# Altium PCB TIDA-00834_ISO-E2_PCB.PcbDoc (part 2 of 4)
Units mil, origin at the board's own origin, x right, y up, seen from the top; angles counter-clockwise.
Board outline 9055.12 x 4133.86 mil, 4 copper layers (Top Layer, GND, PWR, Bottom Layer), stack 61.92 mil thick; 647 components, 282 nets, 1430 pads, 409 vias.
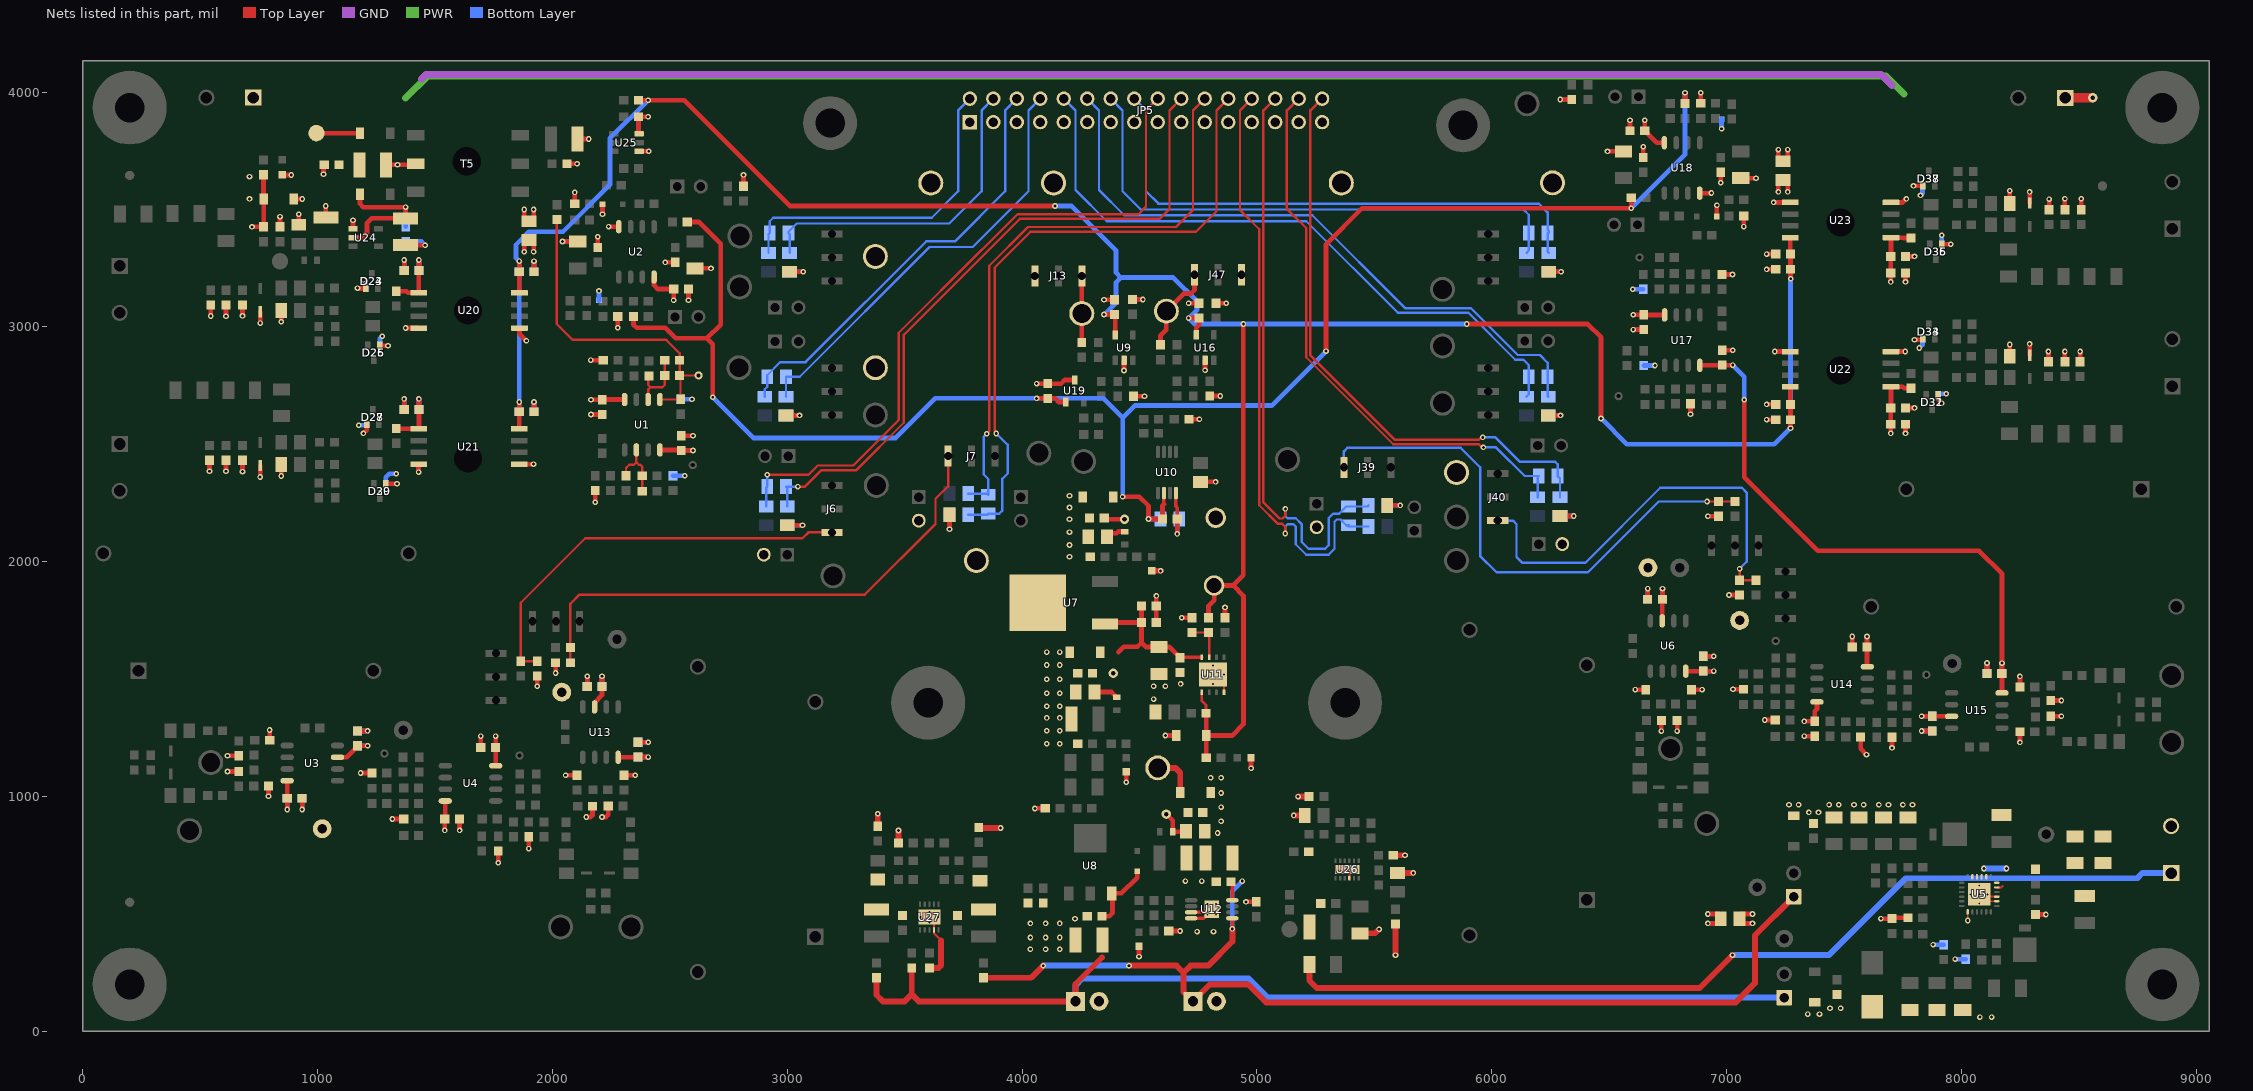
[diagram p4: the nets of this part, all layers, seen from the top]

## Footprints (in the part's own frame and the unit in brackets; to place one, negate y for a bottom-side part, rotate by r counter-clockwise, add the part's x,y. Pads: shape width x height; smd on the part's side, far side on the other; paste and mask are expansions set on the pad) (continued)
DIO_SOD323 [mm] "TVS DIODE, SOD323, SMT"
  rect 1.2x0.35 smd: 1(-1.25,0) 2(1.25,0)
  Top Layer region: -0.356,0.25 -0.357,-0.227 0.417,-0.227 0.415,0.25
  silkscreen extent -5.03,-0.65 1.25,0.65, body extent -1.25,-0.63 1.25,0.63, height 1.1
DSC0010J [mm] "SON, 10-Leads, Body 3x3mm, Pitch 0.5mm, Thermal Pad 2.4x1.65mm, TI Recommended"
  rrect100% 0.6x0.24 smd: 1(-1.4,1) 2(-1.4,0.5) 3(-1.4,0) 4(-1.4,-0.5) 5(-1.4,-1) 6(1.4,-1) 7(1.4,-0.5) 8(1.4,0) 9(1.4,0.5) 10(1.4,1)
  rrect6% 1.65x2.4 smd paste-0.825: 11(0,0)
  silkscreen extent -1.7,-1.7 1.7,1.7, body extent -1.57,-1.57 1.57,1.57, height 0.81
DSS0012B [mm] "SON, 12-Leads, Body 2x3mm, Pitch 0.5mm, Thermal Pad 2.65x1.0mm, TI Recommended"
  rrect40% 0.5x0.25 smd: 1(-0.95,1.25) 2(-0.95,0.75) 3(-0.95,0.25) 4(-0.95,-0.25) 5(-0.95,-0.75) 6(-0.95,-1.25) 7(0.95,-1.25) 8(0.95,-0.75) 9(0.95,-0.25) 10(0.95,0.25) 11(0.95,0.75) 12(0.95,1.25)
  rrect11% 0.949x1.168 on Top Paste: 13(0,0.684) 13(0,-0.684)
  rrect11% 1x2.65 smd paste-0.5: 13(0,0)
  silkscreen extent -1.05,-1.7 1.05,1.7, body extent -1,-1.5 1,1.5, height 0.81
DWV0008A [mm] "SOIC, 8-Leads, Body 5.95x7.6mm (max), Pitch 1.27mm"
  rrect17% 1.8x0.6 smd: 1(-5.45,1.905) 2(-5.45,0.635) 3(-5.45,-0.635) 4(-5.45,-1.905) 5(5.45,-1.905) 6(5.45,-0.635) 7(5.45,0.635) 8(5.45,1.905)
  silkscreen extent -6.25,-2.95 2.98,2.95, body extent -5.77,-2.92 5.77,2.93, height 2.67
FCC_disclaimer [mil]
Fiducial10-20 [mm]
  round 1 smd mask+0.5: 1(0,0)
  Top Layer keep-out circle w1.178: c0,0 r0.5
HDR100_1X2 [mil]
  rect 60x60 hole 38: 1(0,0)
  round 60 hole 38: 2(100,0)
  silkscreen extent -50,-50 150,50
IEC_HighVoltage_Large [mil]
  silkscreen extent -365,-159 323,250
IND_VLF504012 [mm] "TDK"
  rect 1.3x2.2 smd: 1(-1.45,0) 2(1.45,0)
  silkscreen extent -2.2,-2.7 2.2,2.7, body extent -2.15,-2.65 2.15,2.65, height 1.2
Keystone1573-2#1 [mm] "Double Turret"
  round 2.7 hole 2.05: 1(0,0)
  silkscreen extent -1.73,-1.73 1.73,1.73, body extent -1.18,-1.18 1.17,1.18, height 4.72
Keystone1573-2#2 [mm] "Double Turret"
  round 2.7 hole 2.05: 1(4.318,13.335)
  silkscreen extent 2.59,11.61 6.05,15.06, body extent 3.14,12.16 5.49,14.51, height 4.72
Keystone5001 [mil] "For Keystone 500x miniature loop terminals"
  round 80 hole 40: 1(0,0)
  silkscreen extent -58,-58 58,58, body extent -49,-49 49,49, height 182
Keystone5002 [mil] "For Keystone 500x miniature loop terminals"
  round 80 hole 40: 1(0,0)
  silkscreen extent -58,-58 58,58, body extent -49,-49 49,49, height 182
Keystone5010 [mil] "Keystone Multipurpose loops"
  round 87 hole 63: 1(0,0)
  silkscreen extent -70,-70 70,70, body extent -63,-63 63,62, height 319
Keystone5126 [mil] "Keystone Multipurpose loops"
  round 87 hole 63: 1(0,0)
  silkscreen extent -70,-70 70,70, body extent -63,-63 63,62, height 319
Keystone_1891 [mil] "3/16 Hex Female Standoff"
  body extent -108,-93 108,94, height 245
Keystone_1902C#1 [mil] "Hex Standoff, 4-40 threaded, nylon"
  body extent -145,-126 146,126, height 501
Keystone_1902C#2 [mil] "Hex Standoff, 4-40 threaded, nylon"
  round 1 on Mech4: 0(0,0)
  body extent -145,-126 146,126, height 501
KVU_1 [mm]
  rect 1.2x2.8 smd: 1(-2.29,-3.635) 3(2.29,-3.635)
  rect 6.096x6.096 smd: 2(0,3.635)
  silkscreen extent -4.62,-6.78 3.43,7.22
Label_650x200 [mil] "Thermal Transfer Label"
  silkscreen extent -325,-100 325,100, body extent -325,-100 325,100, height 1
LED0603AA [mil]
  rect 32x32 smd: 1(-32.48,0) 2(32.48,0)
  silkscreen extent -16,-74 58,16
"LG L29K_GREEN" [mm] "OSRAM"
  rect 0.8x0.8 smd: 1(-0.75,0) 2(0.75,0)
  silkscreen extent -0.1,-0.5 1.45,0.5, body extent -0.9,-0.45 0.9,0.45, height 0.67
MMZ1608_095 [mm] "TDK"
  rect 0.6x0.8 smd: 1(-0.7,0) 2(0.7,0)
  silkscreen extent -0.15,-0.58 0.15,0.58, body extent -0.87,-0.47 0.87,0.47, height 0.95
"NY PMS 440 0025 PH" [mm] "4-40 nylon screw and mounting hole"
  round 8 hole 3.2: 1(0,0)
  body extent -3.3,-3.3 3.3,3.3, height 2.69
Pb-Free_Overlay_Small [mil]
  silkscreen extent -46,-46 46,46
PogoPad [mil] "No Solder Paste"
  round 70 smd paste-35: 1(0,0)
POWERMITE [mil] "On Semi recommended land pattern, 457-04.pdf Rev 04E dated 2008-11-26"
  rect 105x100 smd: 1(-46,0)
  rect 30x50 smd: 2(46,0)
  silkscreen extent -124,-63 61,63, body extent -94,-40 59,40, height 45
RGE0024B [mm] "QFN, 24-Leads, Body 4x4mm, Pitch 0.5mm, Thermal Pad 2.45x2.45mm, TI Recommended"
  oval 0.6x0.24 smd: 1(-1.9,1.25) 2(-1.9,0.75) 3(-1.9,0.25) 4(-1.9,-0.25) 5(-1.9,-0.75) 6(-1.9,-1.25) 13(1.9,-1.25) 14(1.9,-0.75) 15(1.9,-0.25) 16(1.9,0.25) 17(1.9,0.75) 18(1.9,1.25)
  oval 0.24x0.6 smd: 7(-1.25,-1.9) 8(-0.75,-1.9) 9(-0.25,-1.9) 10(0.25,-1.9) 11(0.75,-1.9) 12(1.25,-1.9) 19(1.25,1.9) 20(0.75,1.9) 21(0.25,1.9) 22(-0.25,1.9) 23(-0.75,1.9) 24(-1.25,1.9)
  rect 2.45x2.45 smd paste-1.225: 25(0,0)
  silkscreen extent -2.22,-2.22 2.22,2.22, body extent -2.07,-2.07 2.07,2.07, height 1.01
Samtec_SSW-116-01-x-D [mm] "Receptacle, 2.54mm, 16x2, TH"
  rect 1.55x1.55 hole 1.04: 1(-19.05,1.27)
  round 1.55 hole 1.04: 2(-19.05,-1.27) 3(-16.51,1.27) 4(-16.51,-1.27) 5(-13.97,1.27) 6(-13.97,-1.27) 7(-11.43,1.27) 8(-11.43,-1.27) 9(-8.89,1.27) 10(-8.89,-1.27) 11(-6.35,1.27) 12(-6.35,-1.27) 13(-3.81,1.27) 14(-3.81,-1.27) 15(-1.27,1.27) 16(-1.27,-1.27) 17(1.27,1.27) 18(1.27,-1.27) 19(3.81,1.27) 20(3.81,-1.27) 21(6.35,1.27) 22(6.35,-1.27) 23(8.89,1.27) 24(8.89,-1.27) 25(11.43,1.27) 26(11.43,-1.27) 27(13.97,1.27) 28(13.97,-1.27) 29(16.51,1.27) 30(16.51,-1.27) 31(19.05,1.27) 32(19.05,-1.27)
  silkscreen extent -20.57,-2.48 20.57,2.8, body extent -20.57,-2.48 20.57,2.48, height 8.51
SDC08A [mm] "SON, 8-Leads, Body 4x4mm, Pitch 0.8mm, NSC Recommended"
  rect 0.6x0.3 smd paste-0.15 mask+0.051: 1(-1.9,1.2) 2(-1.9,0.4) 3(-1.9,-0.4) 4(-1.9,-1.2) 5(1.9,-1.2) 6(1.9,-0.4) 7(1.9,0.4) 8(1.9,1.2)
  rect 2.6x3 smd paste-1.5 mask+0.051: 9(0,0)
  silkscreen extent -3.02,-2.2 2.35,2.2, body extent -2.05,-2.05 2.05,2.05, height 0.8
SOD-123 [mm] "On Semi recommended land pattern"
  rect 0.915x1.22 smd: 1(-1.637,0) 2(1.637,0)
  silkscreen extent -2.74,-1.17 2.03,1.17, body extent -1.93,-0.9 1.93,0.9, height 1.35
SOD-323 [mm] "NXP recommended land pattern"
  rect 0.6x0.6 smd: 1(-1.1,0) 2(1.1,0)
  silkscreen extent -2.06,-0.86 1.53,0.86, body extent -1.3,-0.67 1.3,0.68, height 1.1
sod-323 [mm] "NXP recommended land pattern"
  rect 0.6x0.6 smd: 1(-1.1,0) 2(1.1,0)
  silkscreen extent -2.06,-0.86 1.53,0.86, body extent -1.3,-0.67 1.3,0.68, height 1.1
SOT-323 [mm] "Zetex recommended land pattern.  March 2007"
  rect 0.8x0.6 smd: 1(-0.8,0.65) 2(-0.8,-0.65) 3(0.8,0)
  silkscreen extent -1.14,-1.22 0.77,1.22, body extent -1.13,-1.13 1.12,1.12, height 1.13
TE_5-146280-3 [mm] "Header, 2.54mm, 3x1, TH"
  rect 0.76x2.29 hole 0.89: 1(-2.54,0) 2(0,0) 3(2.54,0)
  silkscreen extent -3.9,-1.17 3.61,1.17, body extent -3.61,-1.17 3.61,1.17, height 8.13
TH-40 [mil]
  round 75 hole 40: 1(0,0)
TI_Stacked_Overlay_Small [mil]
  silkscreen extent -418,-98 418,98
TP1_PD40_D0.5_S50 [mil]
  round 40 hole 20: 1(0,0)
  silkscreen extent -25,-25 25,25
TP-040_RND [mil]
  round 70 / inner round 62 / far side round 62 hole 40: 1(0,0)
TP_H045P075 [mil] "TP_H0.45P0.75"
  round 35 hole 17.72: 1(0,0)
TSW-102-07-G-S [mm] "Samtec 100mil, 1x2, 230 mil above insulator"
  rrect6% 1.65x1.65 hole 1.016: 1(-1.27,0)
  round 1.65 hole 1.016: 2(1.27,0)
  silkscreen extent -2.54,-1.27 2.54,1.65, body extent -2.54,-1.27 2.54,1.27, height 8.38
Wurth_750313638 [mm] "SMD, 6-Leads, Body 8x9.14mm, Pitch 3.05mm"
  rect 1.9x1.14 smd: 1(-5.655,3.05) 2(-5.655,0) 3(-5.655,-3.05) 4(5.655,-3.05) 5(5.655,0) 6(5.655,3.05)
  silkscreen extent -4,-4.57 4,4.87, body extent -6.35,-4.57 6.35,4.57, height 7.62
XFMR_CR8350-2500-N [mil] "CURRENT TRANSFORMERS, VERTICAL, 4 PIN, THRU"
  rect 69.06x69.06 / inner round 69.06 / far side rect 69.06x69.06 hole 49.37: 1(-250,500)
  round 69.06 hole 49.37: 2(-250,-500) 3(250,650) 4(250,-650)
  silkscreen extent -317,-738 276,738, body extent -276,-738 276,738, height 1535

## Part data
C1 C2 C4 C5 C19 C20 C82 C84 C88 C90 C99 C100 C101 C102 C104 C105: "CAP, CERM, 100pF, 25V, +/-10%, X7R, 0603"
C3 C6 C9 C66 C103 C106 C110: "CAP, CERM, 0.1uF, 25V, +/-5%, X7R, 0603"
C7 C8 C107 C108: "CAP, CERM, 1000pF, 50V, +/-5%, C0G/NP0, 0603"
C10 C11 C109 C111 C120 C121: "CAP, CERM, 0.01uF, 25V, +/-5%, C0G/NP0, 0603"
C12 C18 C43 C75 C81 C85 C92 C98: library part C1608X5R1C105K, "CAP, CERM, 1 µF, 16 V, +/- 10%, X5R, 0603"
C13 C17 C44 C76 C80 C83 C86 C87 C89 C91 C93 C97: "CAP, CERM, 0.1 µF, 25 V, +/- 10%, X8R, AEC-Q200 Grade 0, 0603"
C14 C16 C47 C52 C77 C79 C94 C96: "CAP, CERM, 1000 pF, 50 V, +/- 10%, X7R, 0603"
C15 C48 C54 C70 C74 C78 C95: library part 06031C103JAT2A, "10000pF 100V Ceramic Capacitor X7R 0603"
C21 C22 C23 C24 C112 C113 C114 C115: "CAP, CERM, 0.01 µF, 50 V, +/- 10%, X7R, 0805"
C25: "CAP, TA, 4.7 µF, 25 V, +/- 10%, 2 ohm, SMD"
C26 C27 C28 C29 C36 C38 C39 C40 C41 C156: "CAP, CERM, 4.7 µF, 25 V, +/- 20%, X7R, 1206"
C30 C33 C35 C42 C159 C161 C163: "CAP, CERM, 0.01 µF, 6.3 V, +/- 10%, X7R, 0603"
C31: library part C0603C224K4RACTU, "CAP, CERM, 0.22 µF, 6.3 V, +/- 10%, X7R, 0603"
C32 C34: "CAP, CERM, 10 pF, 50 V, +/- 5%, C0G/NP0, 0603"
C37 C152 C154 C158 C165: "CAP, CERM, 1 µF, 25 V, +/- 10%, X5R, 0603"
C45 C55 C68: library part C2012X5R1H475K125AB, "CAP, CERM, 4.7uF, 50V, +/-10%, X5R, 0805"
C46 C51 C56 C58 C69 C71 C118 C119: "CAP, CERM, 0.1uF, 50V, +/-10%, X7R, 0603"
C49 C50: library part GRM188R61H105KAALD, "CAP, CERM, 1uF, 50V, +/-10%, X5R, 0603"
C53 C116: "CAP, CERM, 0.1uF, 16V, +/-5%, X7R, 0603"
C57 C60 C67 C72: "CAP, CERM, 10uF, 35V, +/-20%, X7R, 1210"
C59: "CAP, CERM, 0.47uF, 50V, 10%, X5R, 0603"
C61 C62: "CAP, CERM, 1uF, 10V, +/-10%, X7R, 0805"
C63 C117: "CAP, CERM, 0.1uF, 10V, +/-10%, X7R, 0603"
C64: "CAP, CERM, 10uF, 16V, +/-20%, X5R, 0603"
C65: library part GRM31CR71E106KA12L, "CAP, CERM, 10uF, 25V, +/-10%, X7R, 1206"
C73 C153 C155 C160 C162: "CAP, CERM, 2.2uF, 10V, +/-10%, X7R, 0805"
C122 C123 C127 C128 C132 C133 C137 C138: library part 06033C104JAT2A, "CAP, CERM, 0.1uF, 25V, +/-5%, X7R, 0603"
C124 C125 C129 C130 C134 C135 C139 C140: "CAP, CERM, 1 µF, 16 V, +/- 10%, X7R, 0603"
C126 C131 C136 C141: "CAP, CERM, 330 pF, 50 V, +/- 10%, C0G/NP0, 0805"
C142 C146 C147 C149 C151 C157 C164: library part GMK325AB7106MM-T, "CAP, CERM, 10uF, 35V, +/-20%, X7R, 1210"
C143 C145 C148 C150 C167: library part C0603C104K5RACTU, "CAP, CERM, 0.1uF, 50V, +/-10%, X7R, 0603"
C144: library part C2012X5R1H475K125AB, "4.7µF ±10% 50V X5R Ceramic Capacitor -55°C ~ 85°C"
C166: "CAP, CERM, 3.3 µF, 35 V, +/- 10%, X5R, 0603"
D1 D2 D3 D9 D15 D16 D17 D18: "DIODE, TVS, BIDIRECTIONAL, 3.3VWM, 26VC, SOD323"
D4 D7: "Diode, Schottky, 20 V, 1 A, POWERMITE"
D5 D6 D11 D13: "Diode, Zener, 15V, 1W, SOD-123"
D8: library part MMSZ4685-V, "Diode, Zener, 3.6V, 500mW, SOD-123"
D10 D12 D14 D44: "LED, Green, SMD"
D19 D20 D21 D22: "Diode, Switching, 100 V, 0.2 A, SOD-323"
D23 D24 D25 D26 D27 D28 D29 D30 D31 D32 D33 D34 D35 D36 D37 D38: library part BAV99WT1G, "Diode, P-N, 70V, 0.2A, SOT-323"
D39 D43: "Diode, Zener, 5.6 V, 500 mW, SOD-123"
D40: library part "LED_LG L29K-G2J1-24-Z", "LED SmartLED Green 570NM"
D41 D42: library part MBR0520LT1G, "Diode, Schottky, 20V, 0.5A, SOD-123"
D45: "Diode, Ultrafast, 100 V, 0.25 A, SOD-323"
FB1 FB2 FB3 L19: "Ferrite Bead, 1000 ohm @ 100 MHz, 0.3 A, 0603"
FID1 FID2 FID3 FID4 FID5 FID6: "Fiducial mark.  There is nothing to buy or mount."
H1 H2 H3 H4 H13 H15: "Machine Screw, Round, #4-40 x 1/4, Nylon, Philips panhead"
H5 H6 H7 H8 H14 H16: "Standoff, Hex, 0.5\"L #4-40 Nylon"
H9 H11: "MACHINE SCREW PAN PHILLIPS 4-40"
H10 H12: "Hex Standoff, #4-40, Aluminum, 1/4\""
J1 J2 J10 J31 J34 J48 J49: "TERMINAL BLOCK 5.08MM VERT 2POS, TH"
J3 J4 J17 J18 J24 J25 J35 J36: "Header, Male 2-pin, 100mil spacing,"
J5 J6 J7 J8 J9 J13 J14 J28 J30 J39 J40 J45 J46 J47: "Header, 2.54mm, 3x1, Gold, TH"
J11 J12: "Terminal Block, 4x1, 2.54mm, TH"
J15 J16: library part TSW-102-07-G-S, "Header, 100mil, 2x1, Gold, TH"
J20 J21 J22 J23 J37 J38 J41 J42: "Header, 100mil, 2x1, Gold, TH"
JP5: library part SSW-116-01-G-D, "Receptacle, 2.54mm, 16x2, Gold, TH"
L1 L2 L5 L6 L7 L8 L9 L10 L11 L12 L13 L14 L15 L16 L17 L18: "Ferrite Bead, 21 ohm @ 100 MHz, 6 A, 0805"
L3 L4: "Inductor, Shielded, Ferrite, 4.7uH, 1.83A, 0.1 ohm, SMD"
LBL1: library part THT-14-423-10, "Thermal Transfer Printable Labels, 0.650\" W x 0.200\" H - 10,000 per roll"
LOGO: library part IEC_HighVoltage, "IEC 61010-1 High Voltage Warning"
Logo1: library part TI_Logo, "Texas Instrument Corporate Signature"
Logo2: library part Pb-Free
Logo3: library part FCC_disclaimer, "FCC_disclaimer"
R1 R3 R14 R17 R138 R140 R151 R154: "RES, 68.0 k, 1%, 0.1 W, 0603"
R2 R4 R5 R7 R11 R16 R139 R141 R142 R144 R148 R153: "RES, 330 k, 1%, 0.25 W, 1206"
R6 R9 R12 R13 R143 R146 R149 R150: "RES, 16.0 k, 1%, 0.1 W, 0603"
R8 R10 R26 R32 R45 R99 R118 R134 R145 R147 R163 R169 R196 R197: "RES, 100 ohm, 1%, 0.1W, 0603"
R15 R18 R152 R155: "RES, 130 k, 1%, 0.1 W, 0603"
R19 R20 R21 R22 R156 R157 R158 R159 R208 R209 R212 R213 R218 R219 R224 R225: "RES, 649, 1%, 0.1 W, 0603"
R23 R29 R160 R166: "RES, 1.00Meg ohm, 1%, 0.1W, 0603"
R24 R30 R36 R40 R47 R48 R80 R86 R90 R94 R101 R102 R107 R111 R120 R121 R123 R127 R136 R137 R161 R167: "RES, 100 k, 1%, 0.1 W, 0603"
R25 R31 R88 R162 R168: "RES, 10.0k ohm, 1%, 0.1W, 0603"
R27 R33 R82 R164 R170 R203: library part RNCF0603TKY10K0, "RES, 10.0k ohm, 1%, 0.1W, 0603"
R28 R34 R165 R171: "RES, 1.00k ohm, 1%, 0.25W, 1206"
R35 R41 R89 R95 R106 R112 R122 R128: "RES, 249, 0.1%, 0.1 W, 0603"
R37 R91 R108 R124: "RES, 169, 1%, 0.1 W, 0603"
R38 R92 R109 R125: "RES, 5.60 k, 0.1%, 0.1 W, 0603"
R39 R93 R110 R126: "RES, 15.0, 1%, 0.1 W, 0603"
R42 R57 R59 R62 R63 R65 R96 R104 R105 R113 R114 R116 R129 R130 R132 R198 R200 R201 R214 R229 R230 R231 R233 R234 R238 R240 R246 R247: "RES, 0, 5%, 0.1 W, 0603"
R43 R97 R115 R131: "RES, 82.0 k, 0.1%, 0.1 W, 0603"
R44 R46 R98 R100 R117 R119 R133 R135: "RES, 8.20 k, 1%, 0.1 W, 0603"
R49 R50 R51 R52 R53 R54 R55 R56 R173 R174 R175 R176 R177 R178 R179 R180: "RES, 1.00 k, 1%, 0.125 W, 0805"
R58: "RES, 0 ohm, 5%, 0.25W, 1206"
R60: "RES, 576 k, 1%, 0.1 W, 0603"
R61 R66 R67: "RES, 49.9 k, 0.1%, 0.1 W, 0603"
R64: library part RC0603FR-07620KL, "RES SMD 620K OHM 1% 1/10W 0603"
R68: library part RT0603DRE071RL, "RES SMD 1 OHM 5% 1/10W 0603"
R69: "RES, 1.0 k, 5%, 0.1 W, 0603"
R70 R103 R172: library part CRCW0805330KJNEA, "RES, 0 ohm, 5%, 0.125W, 0805"
R71: "RES, 300 ohm, 5%, 0.1W, 0603"
R72 R73 R77 R78 R81 R83 R189 R190 R191 R192 R193 R194 R195 R226 R228 R242 R243 R244: "RES, 0 ohm, 5%, 0.1W, 0603"
R74 R84: "RES, 3.9k ohm, 5%, 0.1W, 0603"
R75 R76: "RES, 2.00 k, 1%, 0.25 W, 1206"
R79: "RES, 8.45 k, 1%, 0.1 W, 0603"
R85: "RES, 1.07 M, 1%, 0.1 W, 0603"
R87: "RES, 31.6k ohm, 1%, 0.1W, 0603"
R181 R182 R183 R184 R185 R186 R187 R188: "RES, 100 k, 1%, 0.125 W, 0805"
R199 R205 R215 R221: "RES, 160 k, 1%, 0.1 W, 0603"
R202 R204 R235 R236: "RES, 249 k, 1%, 0.1 W, 0603"
R206 R207 R210 R211 R216 R217 R222 R223: "RES, 12.0, 1%, 0.1 W, 0603"
R220 R232 R237 R239: "RES, 75.0 k, 1%, 0.1 W, 0603"
R227 R241: "RES, 820, 1%, 0.1 W, 0603"
R245: "RES, 0, 5%, 0.25 W, 1206"
T1 T2 T3 T4: "CURRENT TRANSFORMER, 20-1 KHz, 57 OHM, VERTICAL, THRU-4P"
T5: library part 750313734, "Transformer, 340 uH, TH"
TP1 TP57 TP58: library part PogoPad, "Pad for Pogo Pin Connector"
TP2 TP5 TP6 TP11 TP12 TP13 TP14 TP18 TP21 TP25 TP31 TP32 TP33 TP34 TP35 TP36 TP37 TP38 TP42 TP43 TP46 TP47 TP48 TP49 TP50 TP51 TP52 TP53 TP54 TP55 TP56 TP59 TP60 TP61: library part 1573-2, "Terminal, Turret, TH, Double"
TP3 TP4 TP10 TP17 TP28 TP30 TP41 TP44 TP45: "Test Point, O.040 Hole"
TP7 TP8 TP27 TP39: "Test Point, Miniature, White, TH"
TP9 TP26 TP29 TP40: "Test Point, Miniature, Black, TH"
TP15 TP16: "Test Point,  Black, Thru Hole Color Keyed"
TP19 TP20 TP22: library part TP-040_RND, "Test Point 40mil pad 20mil drill"
TP23: library part 5010, "Test Point, Multipurpose, Red, TH"
TP24: library part 5126, "Test Point, Multipurpose, Green, TH"
U1 U4 U14 U17: "0.03 uV/degC, 6 uV Vos, Low Noise, Rail-to-Rail Output, Zero-Drift Operational Amplifier, 4 to 36 V, -40 to 105 degC, 8-pin SOIC (D0008A), Green (RoHS & no Sb/Br)"
U2 U18: library part LM2903D, "Dual Comparator, D0008A"
U3 U6 U13 U15: library part INA188D, "INA188 Precision, Zero-Drift, Rail-to-Rail Out, High Voltage Instrumentation Amplifier, D0008A"
U5: "Postive and Negative Output DC-DC Converter, 2.7 to 5.5 V, -40 to 85 degC, 24-pin QFN (RGE24), Green (RoHS & no Sb/Br)"
U7: "IC, 300-mA 40-V LOW-DROPOUT REGULATOR WITH 25-uA QUIESCENT CURRENT"
U8: "IC,  vvV, 800mA LDO Voltage Regulators"
U9 U16: "20 MHz, Low Noise, RRIO, CMOS Operational Amplifier with Shutdown, 1.8 to 5.5 V, -40 to 125 degC, 5-pin SOT23 (DBV0005A), Green (RoHS & no Sb/Br)"
U10: "Low Noise, Very Low Drift, Precision Voltage Reference, -40 to 125 degC, 8-pin MSOP(DGK), Green (RoHS & no Sb/Br)"
U11: "Series of Adjustable Micropower Voltage Regulators, 8-pin LLP"
U12: "Single Output High PSRR LDO, 200 mA, Adjustable -1.18 to -33 V Output, -3 to -36 V Input, with Ultra-Low Noise, 8-pin MSOP (DGN), -40 to 125 degC, Green (RoHS & no Sb/Br)"
U19: "2.5 V, 50 ppm / degC, 50 uA Series (Bandgap) Voltage Reference, -40 to 125 degC, 3-pin SOT-23 (DBZ), Green (RoHS & no Sb/Br)"
U20 U21 U22 U23: "200 kHz, Fully-Differential Isolation Amplifier, DWV0008A"
U24: "Single Output LDO, 150 mA, Fixed 5 V Output, 2.5 to 24 V Input, with Ultra-Low IQ, 5-pin SOT-23 (DBV), -40 to 125 degC, Green (RoHS & no Sb/Br)"
U25: "LOW-NOISE 1A TRANSFORMER DRIVERS FOR ISOLATED POWER SUPPLIES, DBV0006A"
U26: "Low-Noise Regulated Switched-Capacitor Voltage Inverter and Positive LDO, DSS0012B"
U27: "Wide-VIN (±33 V), 150-mA, Spilt-Rail Output, Positive and Negative LDO Voltage Regulator with Startup Tracking, DSC0010J"
ZZ1: library part AssemblyNoteLabel
ZZ2 ZZ3 ZZ4: library part AssemblyNote

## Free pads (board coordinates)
  round 0 hole 120 slot 550 at 90 deg unplated mask+5: 2(1635,3705) 2(1640,2440) 2(1640,3070) 2(7484,2814) 2(7484,3444)

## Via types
v1: diameter 24, hole 12, Top Layer to Bottom Layer, tented both sides, 388 vias
v2: diameter 19.68, hole 7.87, Top Layer to Bottom Layer, tented top, 15 vias
v3: diameter 19.68, hole 7.87, Top Layer to Bottom Layer, 5 vias
v4: diameter 40, hole 20, Top Layer to Bottom Layer, 1 vias

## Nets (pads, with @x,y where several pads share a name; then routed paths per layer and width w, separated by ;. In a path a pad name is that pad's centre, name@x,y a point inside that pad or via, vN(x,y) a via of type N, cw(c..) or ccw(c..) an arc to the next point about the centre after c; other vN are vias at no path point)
+2.5V: J13.1 R77.1 TP21.1 | length 283.5
  Top Layer w20: R77.1@4254,2933.5 TP21.1@4254,3057 J13.1@4254,3217
+2.5VB: J47.1 R191.1 TP55.1 | length 376.1
  Top Layer w20: R191.1@4589,2923.5 4589,2962 4614,2987 TP55.1@4614,3067 4689,3142 4719,3142 4734,3157 J47.1@4734,3222
+3.3V: C45.1 C46.1 C62.1 C118.1 C119.1 D8.1 FB1.2 R25.2 R31.2 R162.2 R168.2 TP19.1 U10.2 U19.1 | length 7682
  Top Layer w15: 4603.8,2245.2 U10.2@4603.8,2292.4
  Top Layer w20: R31.2@2344.98,3044.57 2344.98,3010.02 2358.61,2996.39 2480.61,2996.39 2526,2951 2658,2951 ; R25.2@2577.02,3446.22 2625.21,3446.22 2717,3354.43 2717,3010 2658,2951 ; v1(2683,2700) 2683,2926 2658,2951 ; v1(4061.76,2695.5) C118.1@4109,2695.5 4140.5,2695.5 4156.24,2679.76 U19.1@4186.6,2679.76 ; C46.1@4349.85,2186 4354.85,2181 TP19.1@4436,2181 ; C45.1@4361.5,2106 4376.5,2121 4401.5,2121 4409.06,2128.56 FB1.2@4436.5,2128.56 ; v1(4428,2277) 4499,2277 4538,2238 v1(4538,2182) C119.1@4597.5,2182 ; C119.1@4597.5,2183.5 4597.5,2238.91 4603.8,2245.2 ; v1(5294,2897) 5294,3352 5447.19,3505.19 v1(6593.51,3505.19) R162.2@6593.51,3550.19 ; R168.2@6822.62,3951.68 v1(6822.62,3996.68)
  Bottom Layer w20: v1(2683,2700) 2856,2527 3462,2527 3630.5,2695.5 v1(4061.76,2695.5) 4345.5,2695.5 4428,2613 ; v1(4428,2277) 4428,2613 ; v1(4538,2182) C62.1@4589,2182 ; v1(5294,2897) 5062,2665 4480,2665 4428,2613 ; v1(6593.51,3505.19) 6822.62,3734.3 v1(6822.62,3996.68)
+5.0V_VDC: C122.1 C124.2 C127.1 C129.2 C132.1 C134.2 C137.1 C139.2 D23.2 D26.2 D27.2 D30.2 D31.2 D34.2 D35.2 D38.2 D39.1 R199.2 R205.2 R215.2 R221.2 R226.2 R227.2 U20.1 U21.1 U22.1 U23.1 | length 8188.4
  Top Layer w20: v1(720.96,3425.96) R226.2@770,3425.96 770.53,3426.5 D39.1@770.53,3534.47 ; D39.1@770,3535 R227.2@770,3647.97 ; R199.2@1334.61,2567.13 1336.1,2565.63 U21.1@1430.04,2565.63 1431.5,2567.09 C127.1@1431.5,2648.5 v1(1431.5,2693.5) ; R205.2@1335,3151.5 1378.5,3151.5 1385,3145 U20.1@1430.43,3145 1430.43,3238.94 C122.1@1431.5,3240 v1(1431.5,3285) ; v1(7698.5,2546.5) C132.1@7698.5,2585 C134.2@7698.5,2655 7699.57,2656.06 U22.1@7699.57,2745 7750,2745 7756.5,2738.5 R215.2@7785,2738.5 ; v1(7698.5,3191.5) C139.2@7698.5,3300 7699.57,3301.06 U23.1@7699.57,3380 7753.8,3380 7755.3,3378.5 R221.2@7785,3378.5
  PWR w30: 1375,3975 1469,4069 7678,4069 7755,3992
  Bottom Layer w20: v1(1175,2581.5) 1206.38,2581.5 D27.2@1209.02,2584.13 ; v1(1195,3200) 1204.41,3190.59 D23.2@1204.41,3163.5 D23.2@1204.41,3159.41 ; D26.2@1265.59,2921.5 1265.59,2950.59 v1(1275,2960) ; D30.2@1290.2,2332.13 1290.2,2360.2 1305,2375 v1(1335,2375) ; C129.2@1431.5,2648.5 v1(1431.5,2693.5) ; C124.2@1431.5,3240 v1(1431.5,3285) ; v1@7825,2915 7834.09,2924.09 D34.2@7834.09,2948.5 ; v1(7825,3560) 7834.09,3569.09 D38.2@7834.09,3595.32 ; D31.2@7900.59,2711.5 7904.09,2715 v1(7935,2715) ; D35.2@7915.59,3351.5 v1(7915.59,3390)
  other v1: 7820,2910 710,3545 710,3640
+5V: C53.2 C116.2 C123.2 C125.1 C128.2 C130.1 C133.2 C135.1 C138.2 C140.1 D43.1 R83.2 R87.2 R228.2 R241.2 TP23.1 U9.5 U11.1 U16.5 U20.8 U21.8 U22.8 U23.8 | length 11656.5
  Top Layer w12: U11.1@4765.16,1444.57 4765.16,1407.24 4782.6,1389.8 R83.2@4782.6,1355
  Top Layer w20: v1(1858.5,2680) C128.2@1858.5,2638.5 1859.17,2637.83 U21.8@1859.17,2565.63 ; v1(1858.5,3280) C123.2@1858.5,3235 1858.5,3146.06 U20.8@1859.57,3145 ; R228.2@2366.5,3965 v1(2407.36,3965) 2561,3965 3011,3515 v1(4140,3515) ; v1(4348.8,3052.5) C53.2@4393,3052.5 4396.6,3048.91 U9.5@4396.6,2965.82 ; v1(4708.8,3037.5) C116.2@4753,3037.5 ; U16.5@4741.6,2966.13 4741.6,2996.6 4753,3008 C116.2@4753,3037.5 ; C116.2@4753.91,3036.6 C116.2@4753,3037.5 ; R83.2@4782.6,1355 4784.47,1353.13 D43.1@4784.47,1260 ; R241.2@4783.5,1165 4784.47,1165.96 D43.1@4784.47,1260 ; R87.2@4793.7,1761.5 4793.7,1812.69 4817.4,1836.39 TP23.1@4817.4,1898.87 4898.53,1898.87 ; v1(4942,3012) 4942,1942.35 4898.53,1898.87 ; v1(5893,3012) 6408,3012 6465,2955 v1(6465,2610) ; U22.8@7270.43,2745 7270.43,2671.06 C135.1@7271.5,2670 C133.2@7271.5,2605 v1(7271.5,2568.5) ; U23.8@7270.43,3380 7270.43,3311.06 C140.1@7271.5,3310 C138.2@7271.5,3245 7271.5,3206.5 v1(7272.99,3205) ; D43.1@4784.47,1260 4895,1260 4942.4,1307.4 4942.4,1855 4898.53,1898.87
  Bottom Layer w20: C130.1@1858.5,2638.5 v1(1858.5,2680) C125.1@1858.5,3235 v1(1858.5,3280) 1844.89,3293.62 1844.89,3349.89 1900,3405 2045,3405 2245,3605 2245,3802.64 v1(2407.36,3965) ; v1(4140,3515) 4210,3515 4400,3325 4400,3230 4420,3210 ; v1(4348.8,3052.5) 4400,3103.7 4400,3190 4420,3210 ; v1(5893,3012) v1(4942,3012) 4734.31,3012 v1(4708.8,3037.5) 4745,3073.7 4745,3108.5 4643.5,3210 4420,3210 ; v1(6465,2610) 6575,2500 7202.99,2500 v1(7271.5,2568.5) 7271.5,3203.5 v1(7272.99,3205)
+5V_IN: C26.1 C38.1 J10.1 L3.1 R68.1 R245.2 U5.5 U5.6 U5.8 U5.9 U5.10 U5.11 | length 4091.4
  Top Layer w8: U5.5@8150.39,613.19 8169.45,613.19 8175.12,618.86
  Top Layer w25: R245.2@5222.91,300 R245.2@5222.91,285 5222.91,217.09 5255,185 6885,185 v1(7025,325)
  Bottom Layer w25: v1(7025,325) 7435,325 7762.26,652.26 8748,652.26 8770.07,674.33 J10.1@8892.64,674.33 ; v1(8095.12,693.86) v1(8190.86,693.86)
+6V_VDC: C142.2 C143.1 C149.1 C150.1 D41.1 D42.1 TP58.1 U24.2 | length 840.1
  Top Layer w20: TP58.1@995,3825 D42.1@1180.53,3825 ; U24.2@1150.87,3380 1190,3380 1210,3400 1210,3441.02 1231.06,3462.09 C142.2@1375,3462.09 v1(1375,3510) 1195,3510 1180.53,3524.47 D41.1@1180.53,3565
  Bottom Layer w20: C143.1@1375,3426.5 v1(1375,3510)
+12V: C3.2 C9.2 C17.1 C18.1 C50.1 C51.1 C55.1 C56.1 C65.1 C66.1 C80.1 C81.1 C83.1 C85.1 C86.1 C89.1 C97.1 C98.1 C103.2 C110.2 D11.1 FB2.2 R24.2 R30.2 R82.2 R161.2 R167.2 R198.2 R234.2 TP2.1 TP20.1 U1.8 U2.8 U3.7 U4.8 U6.7 U7.1 U11.8 U13.7 U14.8 U15.7 U17.8 U18.8 | length 2731.1
  Top Layer w15: C66.1@4675.08,1594.17 U11.8@4765.16,1594.17
  Top Layer w20: U3.7@1084.88,1167.52 1123.74,1167.52 1169.41,1213.19 C17.1@1169.41,1216.68 v1(1213.09,1216.68) ; v1(1758.09,1257.45) C86.1@1758.09,1209.27 1758.09,1131.7 U4.8@1758.57,1131.22 ; U13.7@2179.41,1381.92 2179.41,1399.41 2210.91,1430.91 C81.1@2210.91,1469.09 ; R30.2@2192.59,3337.72 v1(2192.59,3383.45) ; C81.1@2209.41,1467.6 C81.1@2210.91,1469.09 ; v1(2210.91,1512.77) C81.1@2210.91,1469.09 ; U2.8@2432.59,3212.29 2432.59,3177.41 2448.78,3161.22 C9.2@2516.1,3161.22 v1(2516.1,3113.04) ; U1.8@2457.38,2476.06 2545.95,2476.06 C3.2@2548.5,2473.5 v1(2598.53,2473.5) ; v1(2480,3274.73) R24.2@2522.59,3274.73 ; C55.1@4307.91,1445 4380.47,1445 FB2.2@4402.91,1422.56 ; U7.1@4353.11,1734.84 4359.73,1741.46 C51.1@4508.5,1741.46 ; 4410,1615 4433,1638 4490.83,1638 4508.5,1655.67 ; C50.1@4508.5,1811.46 C51.1@4508.5,1741.46 ; C66.1@4672.4,1591.5 4626.81,1637.09 C65.1@4582.4,1637.09 4527.09,1637.09 4508.5,1655.67 ; R82.2@4863.7,1761.5 v1(4863.7,1805.69) ; v1(6602.26,3051.5) C103.2@6647.26,3051.5 6647.77,3050.98 U17.8@6735.96,3050.98 ; R161.2@6645,3721.68 v1(6645,3766.68) ; v1(6651.5,3880.19) C110.2@6651.5,3835.19 6702.56,3784.13 U18.8@6735,3784.13 ; U6.7@6725.43,1748.54 6725.43,1839.78 C83.1@6726.3,1840.64 ; C83.1@6726.61,1840.58 v1(6726.61,1885.58) ; v1(6975,3613.69) R167.2@6975,3658.69 ; v1(7597.4,1681.65) C89.1@7597.4,1636.65 7597.4,1554.52 U14.8@7598.77,1553.15 ; v1(7830.12,1342.17) C97.1@7875.12,1342.17 7875.63,1341.65 U15.7@7957.83,1341.65 ; 4508.5,1655.67 C51.1@4508.5,1741.46
  Top Layer w25: R234.2@3385,873.58 v1(3385,927.09) ; v1(5175,1000) R198.2@5222.01,1000
  Bottom Layer w20: C18.1@1169.41,1216.68 v1(1213.09,1216.68) ; C80.1@2210.91,1469.09 v1(2210.91,1512.77) ; C85.1@6726.61,1840.58 v1(6726.61,1885.58) ; v1(7830.12,1342.17) C98.1@7875.18,1342.17
+14V: C57.1 C58.1 D45.1 J11.1 J15.1 R238.1 R246.1 U8.3 | length 4733.3
  Top Layer w20: C58.1@4340,490 4370,490 4385,505 4385,583.8 U8.3@4381,587.8 4422.8,587.8 4490,655 D45.1@4490,681.69
  Top Layer w25: R246.1@3380,228.5 3380,155 3407,128 3500.05,128 3530,157.95 ; R238.1@3530,270.59 3530,157.95 ; 4340,315 4227.4,202.4 J11.1@4227.4,127.95 3560,127.95 3530,157.95
  Bottom Layer w25: J11.1@4227.4,127.95 4227.4,195 4257.4,225 4965,225 5046.14,143.86 J15.1@7245.12,143.86
-12V: C6.2 C12.1 C13.1 C43.1 C44.1 C68.2 C71.1 C75.1 C76.1 C87.1 C91.1 C92.1 C93.1 C106.2 D13.2 FB3.2 R233.2 R240.2 TP22.1 TP42.1 U1.4 U3.4 U4.4 U6.4 U13.4 U14.4 U15.4 U17.4 | length 3926.9
  Top Layer w20: U3.4@870.32,1067.52 870.32,993.3 C13.1@871.1,992.52 v1(871.1,944.88) ; v1(1541.59,856.09) C87.1@1541.59,904.27 1544,906.68 U4.4@1544,981.22 ; v1(2164.2,2689.84) C6.2@2212.38,2689.84 2213.17,2690.63 U1.4@2307.38,2690.63 ; U13.4@2279.41,1167.36 2363.62,1167.36 C76.1@2364.41,1168.14 v1(2408.09,1168.14) ; TP22.1@4613.57,925.33 4640.74,898.17 FB3.2@4640.74,850.13 4695.09,850.13 C68.2@4697.71,852.75 ; U6.4@6825.43,1533.98 6899.95,1533.98 C44.1@6900.18,1534.21 v1(6945.18,1534.21) ; U17.4@6885.96,2836.42 6886.74,2837.2 C106.2@6980.96,2837.2 v1(7025.96,2837.2) ; v1(7075,2690) 7075,2360 7388,2047 8074,2047 8172.4,1948.6 v1(8172.4,1568.14) C93.1@8172.4,1523.14 ; v1(7330.12,1320.35) C91.1@7375.12,1320.35 7375.12,1363.86 7384.2,1372.94 U14.4@7384.2,1403.15 ; C93.1@8171.62,1523.92 C93.1@8172.4,1523.14 ; U15.4@8172.4,1441.65 C93.1@8172.4,1523.14
  Top Layer w25: R240.2@3815,868.58 3817.09,866.5 v1(3908.5,866.5) ; TP42.1@4577.5,1122.5 4652.5,1122.5 4673.24,1101.76 D13.2@4673.24,1017.75 ; v1(5590,325) R233.2@5590,457.01
  Bottom Layer w20: v1(871.1,944.88) C12.1@871.1,992.52 ; C75.1@2364.41,1168.14 v1(2408.09,1168.14) ; C43.1@6900.12,1534.21 v1(6945.18,1534.21) ; v1(7025.96,2837.2) 7075,2788.16 v1(7075,2690) ; C92.1@8171.61,1523.86 8171.61,1567.35 v1(8172.4,1568.14)
-14V: C67.2 C69.1 J12.1 J16.1 R247.1 U12.5 U12.8 | length 4613.8
  Top Layer w15: C69.1@4889.2,637.75 4895,631.96 U12.8@4895,558.65 ; v1(4895,436.71) U12.5@4895,481.88
  Top Layer w25: R247.1@3835,228.5 4038.5,228.5 v1(4090,280) ; v1(4455,280) 4657.4,280 4687.4,250 ; v1(4895,436.71) 4895,382.6 4792.4,280 4717.4,280 4687.4,250 ; J16.1@7285.12,573.86 7120,408.74 7120,205 7038.86,123.86 5038.54,123.86 4962.4,200 4799.45,200 J12.1@4727.4,127.95 4687.4,167.95 4687.4,250
  Bottom Layer w20: v1(4895,436.71) 4895,597.6 v1(4937.4,640)
  Bottom Layer w25: v1(4090,280) v1(4455,280)
ACI_OUT1: C21.1 JP5.18 R49.2 | length 2920.2
  Top Layer w10: v1(2915,2370) 3090,2370 3130,2410 3281,2410 3475,2604 3475,2975 3829.7,3329.7 3830,3329.7 3980.3,3480 4495,3480 4527.4,3512.4 4527.4,3921.85 JP5.18@4577.4,3971.85
  Bottom Layer w10: R49.2@2910,2235 2910,2315 C21.1@2915,2320 v1(2915,2370)
ACI_OUT1_GND: C21.2 JP5.20 R51.2 | length 2918.5
  Top Layer w10: v1(3045,2320) 3075,2320 3144,2389 3293,2389 3496,2592 3496,2966 3990,3460 4585,3460 4627.4,3502.4 4627.4,3921.85 JP5.20@4677.4,3971.85
  Bottom Layer w10: R51.2@3000,2235 3000,2315 C21.2@2995,2320 v1(3045,2320)
ACI_OUT2: C22.1 JP5.22 R50.2 | length 2541.4
  Top Layer w10: v1(3849,2545) 3860.13,2556.13 3860.13,3260.4 4024.72,3425 4655,3425 4727.4,3497.4 4727.4,3921.85 JP5.22@4777.4,3971.85
  Bottom Layer w10: R50.2@3771,2290 3851,2290 C22.1@3856,2285 3856,2352.15 3836,2372.15 3836,2532 v1(3849,2545)
ACI_OUT2_GND: C22.2 JP5.24 R52.2 | length 2763.5
  Top Layer w10: v1(3890,2546) 3883,2553 3883,3253 4035,3405 4740,3405 4827.4,3492.4 4827.4,3921.85 JP5.24@4877.4,3971.85
  Bottom Layer w10: R52.2@3771,2200 3851,2200 C22.2@3856,2205 3902.85,2205 3916,2218.15 3916,2353.15 3938.57,2375.72 3938.57,2497.43 v1(3890,2546)
ACI_OUT3: C112.1 JP5.26 R173.2 | length 2597.1
  Top Layer w10: JP5.26@4977.4,3971.85 4927.4,3921.85 4927.4,3497.6 5009.53,3415.47 5009.53,2240.47 5089,2161 5107.24,2161 5120,2148.24 v1(5120,2120)
  Bottom Layer w10: v1(5120,2120) 5120,2150 5130,2160 5155,2160 5165,2150 5165,2074.64 5209.64,2030 5305,2030 5330,2055 5330,2170 5340,2180 5355,2180 5380,2155 C112.1@5390,2155 5387.5,2152.5 5390,2150 R173.2@5475,2150
ACI_OUT3_GND: C112.2 JP5.28 R175.2 | length 2526.7
  Top Layer w10: JP5.28@5077.4,3971.85 5027.4,3921.85 5027.4,2252.6 5096,2184 5109,2184 5121,2196 v1(5121,2225)
  Bottom Layer w10: v1(5121,2225) 5121,2194 5130,2185 5165.36,2185 5190,2160.36 5190,2085 5220,2055 5290,2055 5305,2070 5305,2185 5325,2205 5350,2205 5380,2235 C112.2@5390,2235 5470,2235 R175.2@5475,2240
ACI_OUT4: C113.1 JP5.30 R174.2 | length 2448
  Top Layer w10: JP5.30@5177.4,3971.85 5127.4,3921.85 5127.4,3502.6 5209.4,3420.6 5209.4,2870.6 5209.53,2870.6 5580.12,2500 5945,2500 5958,2487 v1(5964,2487)
  Bottom Layer w10: v1(5964,2487) 6018,2487 6139.99,2365.01 C113.1@6200,2365.01 6195,2360.01 R174.2@6195,2275.01
ACI_OUT4_GND: C113.2 JP5.32 R176.2 | length 2510.9
  Top Layer w10: JP5.32@5277.4,3971.85 5227.4,3921.85 5227.4,2878 5585.4,2520 5945,2520 5954.5,2529.5 v1(5961.5,2529.5)
  Bottom Layer w10: v1(5961.5,2529.5) 6015.5,2529.5 6120,2425 6270,2425 6280,2415 C113.2@6280,2365.01 6290,2355.01 R176.2@6290,2275.01
ACV_OUT1: C23.1 JP5.2 R53.2 | length 1407.4
  Bottom Layer w10: R53.2@2920,3315 2920,3395 C23.1@2925,3400 2925,3450 2940,3465 3615,3465 3727.4,3577.4 3727.4,3921.85 JP5.2@3777.4,3971.85
ACV_OUT1_GND: C23.2 JP5.4 R55.2 | length 1401
  Bottom Layer w10: R55.2@3010,3315 3010,3395 C23.2@3005,3400 3005,3405 3040,3440 3690,3440 3827.4,3577.4 3827.4,3921.85 JP5.4@3877.4,3971.85
ACV_OUT2: C24.1 JP5.6 R54.2 | length 1848
  Bottom Layer w10: R54.2@2904.43,2703.05 2904.43,2734.43 2914.43,2744.43 C24.1@2914.43,2788.05 2914.43,2794.43 2970,2850 3078,2850 3592,3364 3714,3364 3927.4,3577.4 3927.4,3921.85 JP5.6@3977.4,3971.85
ACV_OUT2_GND: C24.2 JP5.8 R56.2 | length 1860.1
  Bottom Layer w10: R56.2@2994.43,2703.05 C24.2@2994.43,2788.05 3053.05,2788.05 3605,3340 3790,3340 4027.4,3577.4 4027.4,3921.85 JP5.8@4077.4,3971.85
ACV_OUT3: C114.1 JP5.10 R177.2 | length 2787.2
  Bottom Layer w10: JP5.10@4177.4,3971.85 4227.4,3921.85 4227.4,3582.6 4360,3450 5210,3450 5600,3060 5900,3060 6100,2860 6135,2860 6157.38,2837.62 C114.1@6157.38,2788.05 6157.38,2713.05 R177.2@6147.38,2703.05
ACV_OUT3_GND: C114.2 JP5.12 R179.2 | length 2770
  Bottom Layer w10: JP5.12@4277.4,3971.85 4327.4,3921.85 4327.4,3582.6 4435,3475 5235,3475 5630,3080 5910,3080 6110,2880 6205,2880 6237.38,2847.62 C114.2@6237.38,2788.05 6237.38,2705.68 R179.2@6240,2703.05
ACV_OUT4: C115.1 JP5.14 R178.2 | length 2353.1
  Bottom Layer w10: JP5.14@4377.4,3971.85 4427.4,3921.85 4427.4,3577.6 4505,3500 6135,3500 6157.38,3477.62 C115.1@6157.38,3400 6157.38,3325 R178.2@6147.38,3315
ACV_OUT4_GND: C115.2 JP5.16 R180.2 | length 2339
  Bottom Layer w10: JP5.16@4477.4,3971.85 4527.4,3921.85 4527.4,3577.6 4580,3525 6200,3525 6237.38,3487.62 6237.38,3415 6242.38,3410 C115.2@6242.38,3400 ; C115.2@6237.38,3400 6237.38,3320 R180.2@6242.38,3315
AGND: C3.1 C4.2 C5.2 C6.1 C12.2 C13.2 C14.2 C16.1 C17.2 C18.2 C20.2 C43.2 C44.2 C45.2 C46.2 C47.2 C49.2 C50.2 C51.2 C52.1 C53.1 C55.2 C56.2 C57.2 C58.2 C59.2 C60.2 C61.2 C62.2 C63.1 C64.2 C65.2 C66.2 C67.1 C68.1 C69.2 C71.2 C72.1 C73.2 C74.1 C75.2 C76.2 C77.2 C79.1 C80.2 C81.2 C83.2 C84.2 C85.2 C86.2 C87.2 C89.2 C90.2 C91.2 C92.2 C93.2 C94.2 C96.1 C97.2 C98.2 C100.2 C103.1 C104.2 C105.2 C106.1 C116.1 C117.1 C118.2 C119.2 C123.1 C125.2 C128.1 C130.2 C133.1 C135.2 C138.1 C140.2 C166.2 D8.2 D10.2 D11.2 D12.2 D13.1 D14.1 D43.2 D44.2 J13.3 J22.2 J23.2 J41.2 J42.2 J47.3 JP5.1 JP5.3 JP5.5 JP5.7 JP5.9 JP5.11 JP5.13 JP5.15 JP5.17 JP5.19 JP5.21 JP5.23 JP5.25 JP5.27 JP5.29 JP5.31 R15.1 R18.1 R36.1 R40.2 R42.1 R48.1 R51.1 R52.1 R55.1 R56.1 R70.1 R79.1 R80.1 R86.1 R88.1 R90.1 R94.2 R96.2 R102.1 R103.1 R107.1 R111.2 R116.1 R121.1 R123.1 R127.2 R132.2 R137.1 R152.1 R155.1 R172.1 R175.1 R176.1 R179.1 R180.1 R181.1 R182.1 R183.1 R184.1 R185.1 R186.1 R187.1 R188.1 R242.2 R243.2 TP9.1 TP24.1 TP26.1 TP29.1 TP32.1 TP33.1 TP34.1 TP36.1 TP37.1 TP40.1 TP53.1 TP54.1 U7.2 U9.2 U10.4 U11.4 U11.9 U12.3 U12.4 U12.9 U16.2 U19.3 U20.5 U21.5 U22.5 U23.5 | length 6376.4
  Top Layer w10: U11.4@4859.65,1444.57 U11.9@4859.65,1472.13
  Top Layer w15: C51.2@4569.5,1739.46 C51.2@4571.5,1741.46 ; U10.4@4654.98,2292.4 4654.98,2235.61 4660.5,2230.1 C119.2@4660.5,2182 ; U12.4@4719.8,481.88 4773.06,481.88 4794.61,503.42 U12.9@4794.61,507.47 ; U12.3@4719.8,507.47 U12.9@4794.61,507.47 ; v2(4807.4,520.26) U12.9@4794.61,507.47
  Top Layer w20: v1(616.22,1106.53) C14.2@664.41,1106.53 ; v1(616.22,1173.54) C16.1@664.41,1173.54 ; v1(790.9,1001.36) R36.1@790.9,1045.04 ; R40.2@795.9,1240.04 v1(795.9,1283.36) ; v1(934.09,944.88) C13.2@934.09,992.52 ; C17.2@1169.41,1279.67 v1(1213.09,1279.67) ; v1(1183.33,1100.28) R42.1@1231.52,1100.28 ; v1(1318.41,904.27) R48.1@1366.59,904.27 ; v1(1604.59,856.09) C87.2@1604.59,904.27 ; C86.2@1695.1,1209.27 v1(1695.1,1257.45) ; v1(1769.41,718.58) R102.1@1769.41,768.6 ; U21.5@1859.17,2415.63 v1(1919.13,2415.63) ; U20.5@1859.57,2995 1859.57,2970.43 v1(1889,2941) ; v1(1880,3320) 1880,3365 1885,3370 R172.1@1900,3370 1920,3370 v1(1920,3320) ; v1(1899.41,778.52) R96.2@1899.41,828.54 ; C128.1@1921.5,2638.5 v1(1921.5,2680) ; C123.1@1921.5,3235 v1(1921.5,3280) ; v1(1935,1469.82) C20.2@1935,1513.5 ; v1(2013.5,1526.32) C84.2@2013.5,1570 ; v1(2056.23,1090.58) R94.2@2104.41,1090.58 ; v1(2143.67,913.09) 2163.09,913.09 2170.91,920.91 C79.1@2170.91,959.09 ; C81.2@2147.91,1469.09 v1(2147.91,1512.77) ; v1(2162.93,2858.35) R15.1@2212.96,2858.35 ; v1(2164.2,2626.85) C6.1@2212.38,2626.85 ; v1(2182.38,2253.17) R18.1@2182.38,2303.19 ; v1(2210.81,913.09) 2228.09,913.09 2237.91,922.91 C77.2@2237.91,960.04 ; R90.1@2304.41,1090.58 v1(2352.59,1090.58) ; C76.2@2364.41,1231.14 v1(2408.09,1231.14) ; C3.1@2548.5,2536.5 v1(2598.53,2536.5) ; R185.1@2994.43,2623.05 v1(3052,2623.05) ; R181.1@2995,2165 R181.1@3000,2165 ; R181.1@3000,2155 v1(3065,2155) ; R188.1@3010,3235 v1(3068,3235) ; v1(3691,2138.15) R182.1@3691,2200 ; v1@4053.98,950 C166.2@4098.5,950 ; v1(4061.76,2758.5) C118.2@4109,2758.5 4165.5,2758.5 4181.24,2774.24 U19.3@4224,2774.24 ; v1(4348.8,3115.5) C53.1@4393,3115.5 ; v1(4434,2814) U9.2@4434,2857.55 ; v1@4442.91,1060.94 D12.2@4442.91,1105.47 ; R242.2@4470,3116.5 v1(4514.2,3116.5) ; C63.1@4474,2704.76 v1(4521.24,2704.76) ; v1(4497.64,318.62) D14.1@4497.64,363.03 ; C51.2@4571.5,1741.46 C50.2@4571.5,1811.46 v1(4571.5,1854.46) ; v1@4589.35,1961.47 v1(4589.82,1961) ; v1(4610,1260) D43.2@4655.53,1260 ; R86.1@4624.2,427.75 v1(4672.71,427.75) ; v1(4660.5,2118.5) C119.2@4660.5,2182 ; v1(4679.5,1761.5) R88.1@4723.7,1761.5 ; v1(4708.8,3100.5) C116.1@4753,3100.5 ; C64.2@4710.5,2607 v1(4754.69,2607) ; C61.2@4759,2340 v1(4824,2340) ; v1(4779,2815) U16.2@4779,2857.87 ; C117.1@4799,2705.5 v1(4843.2,2705.5) ; R243.2@4825,3100.5 v1(4869.2,3100.5) ; v1(4952.94,551.76) C74.1@4996.44,551.76 ; v1@4974.53,1120.47 D44.2@4974.53,1165 ; R183.1@5555,2240 v1(5610,2240) ; R186.1@6240,2623.05 v1(6292.63,2623.05) ; R187.1@6242.38,3235 v1(6295,3235) ; R184.1@6290,2195 v1(6349,2195.01) ; v1(6602.26,2988.5) C103.1@6647.26,2988.5 ; v1(6610.44,1455.35) R111.2@6655.44,1455.35 ; C83.2@6663.62,1840.58 v1(6663.62,1885.58) ; v1(6721.93,1278.86) C52.1@6721.93,1323.86 ; v1(6788.94,1278.86) C47.2@6788.94,1323.86 ; v1(6845.96,2627.83) R152.1@6845.96,2672.83 ; R107.1@6850.44,1455.35 v1(6895.44,1455.35) ; C44.2@6900.18,1597.2 v1(6945.18,1597.2) ; v1(6920,460) 6970,460 6975,465 R70.1@6975,480 6975,495 6970,500 v1(6920,500) ; v1(6920,2193.5) C90.2@6965,2193.5 ; R155.1@6980,3223.35 v1(7025,3223.35) ; C106.1@6980.96,2900.19 v1(7025.96,2900.19) ; v1(7010,1858.5) C100.2@7055,1858.5 ; v1(7026.71,1457.2) R116.1@7071.71,1457.2 ; v1(7161.79,1326.2) R121.1@7206.79,1326.2 ; v1(7170,2605) C133.1@7208.5,2605 ; v1(7170,2670) C135.2@7208.5,2670 ; v1(7170,3245) C138.1@7208.5,3245 ; v1(7170,3310) C140.2@7208.5,3310 ; v1(7200,3530) U23.5@7270.43,3530 ; v1(7205,2895) U22.5@7270.43,2895 ; v1(7220,3575) 7220,3620 7225,3625 R103.1@7240,3625 7260,3625 v1(7260,3575) ; v1(7330.12,1257.36) C91.2@7375.12,1257.36 ; C89.2@7534.41,1636.65 v1(7534.41,1681.65) ; R137.1@7570.32,1253.86 7570.32,1203.66 v1(7595.12,1178.86) ; v1(7703.82,1207.36) R132.2@7703.82,1252.36 ; v1(7830.18,1279.18) C97.2@7875.12,1279.18 C97.2@7875.18,1279.18 ; C93.2@8108.63,1523.92 v1(8108.63,1568.92) ; v1(8248.62,1230.67) R127.2@8248.62,1275.67 ; R123.1@8248.62,1466.65 v1(8248.62,1511.65) ; C96.1@8380.12,1342.17 v1(8425.12,1342.17) ; C94.2@8380.12,1409.18 v1(8425.12,1409.18)
  Top Layer w25: D10.2@4552.14,1961.47 v1@4589.35,1961.47
  Bottom Layer w20: v1(934.09,944.88) C12.2@934.09,992.52 ; C18.2@1169.41,1279.67 v1(1213.09,1279.67) ; C130.2@1921.5,2638.5 v1(1921.5,2680) ; C125.2@1921.5,3235 v1(1921.5,3280) ; C80.2@2147.91,1469.09 v1(2147.91,1512.77) ; C75.2@2364.41,1231.14 v1(2408.09,1231.14) ; C5.2@2513.31,2366.3 v1(2563.33,2366.3) ; C4.2@2546.08,2691.5 v1(2594.26,2691.5) ; R56.1@2994.43,2623.05 v1(3052,2623.05) ; R51.1@3000,2155 v1(3065,2155) ; R55.1@3010,3235 v1(3068,3235) ; v1(3691,2138.15) R52.1@3691,2200 ; v1(4660.5,2118.5) 4660.5,2173.5 C62.2@4669,2182 ; R175.1@5555,2240 v1(5610,2240) ; R179.1@6240,2623.05 v1(6292.63,2623.05) ; R180.1@6242.38,3235 v1(6295,3235) ; R176.1@6290,2195.01 v1(6349,2195.01) ; v1(6599.84,3160.55) C105.2@6644.84,3160.55 ; C104.2@6647.26,2835.55 v1(6694.45,2835.55) ; C85.2@6663.62,1840.58 v1(6663.62,1885.58) ; C43.2@6900.12,1597.2 v1(6945.18,1597.2) ; v1(7830.18,1279.18) C98.2@7875.18,1279.18 ; C92.2@8108.62,1523.86 v1(8108.63,1568.92)
  other v1: 4035,350 4100,350 4160,350 4035,400 4100,400 4160,400 4745,425 4815,425 4035,460 4100,460 4160,460 4225,480 4695,640 4765,640 4832.4,845 4847.4,895 4054.45,949.53 4847.4,955 4847.4,1015 4443.39,1061.42 4802.4,1080 4847.4,1080 4975,1120.94 4105,1225 4160,1225 4105,1280 4160,1280 4105,1335 4160,1335 4105,1385 4160,1385 4560,1415 4105,1440 4160,1440 4560,1470 4610,1470 4675,1480 4105,1500 4160,1500 4105,1560 4160,1560 4105,1615 4160,1615 4201.5,2021 4201.5,2071 4201.5,2126 4201.5,2181 4201.5,2231 4201.5,2281
  other v2: 4789.69,496.64 4825.12,496.64 4789.69,543.88 4825.12,543.88 4812.4,1480 4765.16,1519.37 4812.4,1519.37 4859.65,1519.37 4812.4,1558.74
CT_1_OUT: C20.1 J6.3 R45.2 | length 1776
  Top Layer w10: R45.2@1860,1568.78 1867.72,1576.5 C20.1@1935,1576.5 ; R45.2@1865,1576.5 1865,1825 2140,2100 3065,2100 3090,2125 J6.3@3190,2125
CT_2_OUT: C84.1 J7.3 R99.2 | length 2258
  Top Layer w10: C84.1@2076.5,1570 R99.2@2076.5,1635 2076.5,1821.5 2115,1860 3330,1860 3631,2161 3631,2268.15 3685,2322.15 J7.3@3685,2450
CT_3_OUT: C90.1 J39.3 R118.2 | length 2304.6
  Top Layer w10: v1(6916.5,2256.5) C90.1@6965,2256.5 R118.2@7035,2256.5
  Bottom Layer w10: J39.3@5370,2401.85 5370,2470 5385,2485 5867,2485 5950,2402 5950,2025 6020,1955 6409,1955 6710.5,2256.5 v1(6916.5,2256.5)
CT_4_OUT: C100.1 J40.3 R134.2 | length 1813.3
  Top Layer w10: v1(7055,1970) C100.1@7055,1921.5 R134.2@7125,1921.5
  Bottom Layer w10: J40.3@6025,2175.01 6089.99,2175.01 6105,2160 6105,2020 6130,1995 6397.5,1995 6717.5,2315 7065,2315 7085,2295 7085,2000 v1(7055,1970)
GND: C9.1 C10.1 C11.1 C120.1 C147.1 C148.1 C167.1 D19.2 D20.2 R28.1 R34.1 R172.2 U2.4 U25.4 U25.6 | length 836.2
  Top Layer w20: v1(1880,3500) 1880,3455 1885,3450 R172.2@1900,3450 1920,3450 v1(1920,3500) ; v1(2042.73,3363.31) R34.1@2107.59,3363.31 ; C148.1@2061.5,3695 v1(2105,3695) ; C10.1@2094.98,3524.57 v1(2094.98,3572.75) ; C147.1@2107.09,3800 v1(2155,3800) ; v1(2213.17,3479.41) D19.2@2213.17,3522.72 ; v1(2239.19,3426.85) U2.4@2282.59,3426.85 ; v1(2277.97,2996.39) C11.1@2277.97,3044.57 ; U25.4@2369.13,3747.6 v1(2410,3747.6) ; U25.6@2369.13,3822.4 2366.5,3825.04 C167.1@2366.5,3895 v1(2407.36,3895) ; v1(2579.09,3113.04) C9.1@2579.09,3161.22 ; R28.1@2607.59,3249.14 v1(2675.05,3249.14) ; C120.1@2813.52,3598.78 v1(2813.52,3647.05)
  Bottom Layer w20: D20.2@2198.17,3112.72 v1(2198.17,3153.17)
GND1: C25.2 C26.2 C27.2 C28.2 C29.2 C30.2 C31.1 C33.1 C35.2 C36.2 C37.2 C38.2 C39.2 C40.2 C41.2 C42.2 C151.1 C152.2 C153.2 C155.2 C156.2 C157.1 C158.2 C160.2 C162.2 C163.2 C164.1 C165.2 D5.2 D6.1 J10.2 J11.2 J12.2 L4.2 R61.2 R70.2 R220.1 R232.1 R237.1 U5.2 U5.3 U5.19 U5.25 U26.4 U26.13@5383.66,689.84 U27.4 U27.11 | length 1163.8
  Top Layer w8: v3(5383.66,689.84) U26.13@5393.5,680 ; v1(8026.38,472.6) U5.19@8026.38,508.86 ; U5.25@8105.12,554.13 U5.2@8150.39,554.13
  Top Layer w9: U27.11@3605,487.09 3624.69,467.4 U27.4@3624.69,431.97 3624.69,417.4 3655,387.09 ; U26.4@5393.5,652.44 U26.13@5393.5,680 ; U5.25@8085.43,573.82 U5.3@8150.39,573.82
  Top Layer w20: v1(7110,460) 7060,460 7055,465 R70.2@7055,480 7055,495 7060,500 v1(7110,500) ; v1(7656.61,480.35) C33.1@7703.62,480.35 ; C33.1@7707.13,483.86 C31.1@7772.13,483.86 ; C37.2@8315.12,497.83 v1(8359.09,497.83)
  Top Layer w25: R237.1@3473.5,802.09 v1(3473.5,855.59) ; C163.2@3605,270.59 3643.5,270.59 3655,282.09 3655,387.09 ; v1(5156.5,920) C153.2@5203.5,920 ; C156.2@5438.5,417.91 5502.91,417.91 v1(5520,435) ; R232.1@5580,750 v1(5630,750) ; C155.2@5598.5,675 v1(5665,675)
  Bottom Layer w20: v1(7879.13,369.53) C42.2@7923.94,369.53 ; v1(7972.83,307.83) R61.2@8017.64,307.83
  other v1: 8078.12,60.86 8128.12,60.86 7345.12,73.86 7395.12,73.86 7440.12,98.86 7485.12,98.86 7350.12,932.86 7391.12,932.86 7265.12,964.86 7306.12,964.86 7436.12,964.86 7477.12,964.86 7542.12,964.86 7583.12,964.86 7648.12,964.86 7689.12,964.86 7750.12,964.86 7791.12,964.86
  other v2: 8075.59,545.28 8110.97,583.36 8037.2,583.66 8075.59,583.66 8075.59,622.05
  other v3: 3605,464.45 3567.6,487.09 3642.4,487.09 3605,509.72
GND2: C109.1 C110.1 C111.1 C121.1 D21.2 D22.2 R103.2 R165.1 R171.1 U18.4 | length 593.5
  Top Layer w20: v1(6291.5,3968.5) C121.1@6340,3968.5 ; v1(6492.27,3747.27) R165.1@6560,3747.27 ; C110.1@6588.51,3835.19 v1(6588.51,3880.19) ; U18.4@6885,3569.56 6934.56,3569.56 v1(6935,3570) ; C111.1@6889.63,3951.84 v1(6889.63,3996.84) ; D21.2@6958.31,3470 v1(6958.31,3518.31) ; R171.1@7060,3633.1 v1(7125,3633.1) ; v1(7072.62,3426.84) C109.1@7072.62,3471.84 ; v1(7220,3755) 7220,3705 R103.2@7240,3705 7255,3705 7260,3710 v1(7260,3755)
  Bottom Layer w20: v1(6978.31,3843.31) D22.2@6978.31,3885
GND_VDC: C7.1 C8.1 C107.1 C108.1 C122.2 C124.1 C127.2 C129.1 C132.2 C134.1 C137.2 C139.1 C142.1 C143.2 C144.1 C145.2 C146.1 C149.2 C150.2 D1.2 D2.2 D17.2 D18.2 D24.1 D25.1 D28.1 D29.1 D32.1 D33.1 D36.1 D37.1 D39.2 D40.1 J48.1 J49.1 L11.1 L12.1 L15.1 L16.1 R19.1 R20.1 R21.1 R22.1 R156.1 R157.1 R158.1 R159.1 T5.5 U20.4 U21.4 U22.4 U23.4 U24.1 | length 8813.4
  Top Layer w20: v1(540,2385) R22.1@540,2432.01 ; v1(545,3046.5) R20.1@545,3093.5 ; v1(610,2385) R21.1@610,2432.01 ; v1(610,3045.32) R19.1@610,3093.5 ; v1(680,2383.83) C8.1@680,2432.01 ; v1(680,3046.76) C7.1@680,3094.94 ; v1(755.45,2360.98) D2.2@755.45,2409.29 ; v1(755.48,3016.2) D1.2@755.48,3064.5 ; C145.2@840,3425.96 v1(840,3469.47) ; v1(845,2365.32) L12.1@845,2413.5 ; v1(845,3021.82) L11.1@845,3070 ; D40.1@850,3646.99 v1(887.48,3646.99) ; D39.2@899.47,3544.47 v1(935,3544.47) ; C144.1@920,3434.47 v1(920,3479.47) ; v1(1025,3650) 1025,3686.5 C150.2@1028.5,3690 ; C146.1@1035,3466.56 v1(1035,3514.47) ; U24.1@1150.87,3417.4 v1(1150.87,3454.13) ; v1(1170,3165) 1175,3165 1176.5,3163.5 D24.1@1204.41,3163.5 ; v1(1195,2546.5) 1209.02,2560.51 D28.1@1209.02,2584.13 ; D25.1@1265.59,2921.5 1267.09,2920 v1(1300,2920) ; D29.1@1290.2,2332.13 v1(1338.38,2332.13) ; C149.2@1292.09,3690 v1(1340,3690) 1412.36,3690 T5.5@1417.36,3695 ; C127.2@1368.5,2648.5 v1(1368.5,2693.5) ; C122.2@1368.5,3240 v1(1368.5,3285) ; v1(1375,2995) U20.4@1430.43,2995 ; C142.1@1375,3347.91 v1(1457.91,3347.91) ; v1(1430,2381.5) v1(1430,2381.5) U21.4@1430.04,2415.63 ; U22.4@7699.57,2895 v1(7760,2895) ; U23.4@7699.57,3530 7750,3530 v1(7765,3545) ; v1(7761.5,2546.5) C132.2@7761.5,2585 ; C134.1@7761.5,2655 v1(7800,2655) ; v1(7761.5,3191.5) C137.2@7761.5,3230 ; C139.1@7761.5,3300 v1(7800,3300) ; v1(7795.59,3600.32) D37.1@7834.09,3600.32 ; v1(7800,2945) 7830.59,2945 D33.1@7834.09,2948.5 ; D32.1@7900.59,2711.5 7900.59,2689.41 v1(7915,2675) ; D36.1@7915.59,3351.5 v1(7954.09,3351.5) ; L15.1@8205,2875 v1(8205,2925) ; L16.1@8205,3525 v1(8205,3580) ; D17.2@8290,2879.21 v1(8290,2927.52) ; D18.2@8290,3526.69 v1(8290,3575) ; C107.1@8370,2851.5 v1(8370,2895) ; C108.1@8372.95,3498.98 v1(8372.95,3543.98) ; R156.1@8440,2851.5 v1(8440,2895) ; R158.1@8440,3498.98 v1(8440,3545.98) ; R157.1@8505,2851.5 v1(8505,2895) ; R159.1@8510,3498.98 v1(8510,3545.98)
  Top Layer w40: J49.1@8441.5,3975.24 v4(8558.74,3975.24)
  GND w30: 1443,4056 1461,4074 5948,4074 7658,4074 7703.5,4028.5
  Bottom Layer w20: C129.1@1368.5,2648.5 v1(1368.5,2693.5) ; C124.1@1368.5,3240 v1(1368.5,3285) ; C143.2@1375,3363.5 1442.32,3363.5 v1(1457.91,3347.91)
"LDO FB": R87.1 R88.2 U11.7 | length 175.6
  Top Layer w10: R88.2@4723.7,1698.5 R87.1@4793.7,1698.5 4796.65,1695.55 U11.7@4796.65,1594.17
NetC1_1: C1.1 R1.2 R6.1 U1.2 | length 280.2
  Top Layer w10: U1.2@2407.38,2690.63 2407.38,2733.34 2417.38,2743.35 ; R6.1@2411.63,2791.22 2407.38,2786.97 2407.38,2753.35 2417.38,2743.35 ; R1.2@2478.48,2857.72 C1.1@2478.48,2792.72 2478.48,2753.44 2468.38,2743.35 2417.38,2743.35
NetC1_2: C1.2 R1.1 R8.1 R229.2 TP3.1 U1.1 | length 1388.3
  Top Layer w10: R229.2@2020,3457.5 2017.86,3455.36 2017.86,3013.14 2086,2945 2484,2945 2541.48,2887.52 C1.2@2541.48,2792.72 ; U1.1@2457.38,2690.63 2545.22,2690.63 2545.22,2788.98 C1.2@2541.48,2792.72 ; TP3.1@2622.38,2793.34 2621.76,2792.72 C1.2@2541.48,2792.72
NetC2_1: C2.1 R3.2 R9.1 U1.6 | length 277.4
  Top Layer w10: R9.1@2313.5,2366.18 2313.5,2399.47 2327.38,2413.35 2347.38,2413.35 2357.38,2423.34 ; U1.6@2357.38,2476.06 2357.38,2423.34 ; R3.2@2382.01,2300 C2.1@2382.01,2366.3 2382.01,2405.72 2374.38,2413.35 2367.38,2413.35 2357.38,2423.34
